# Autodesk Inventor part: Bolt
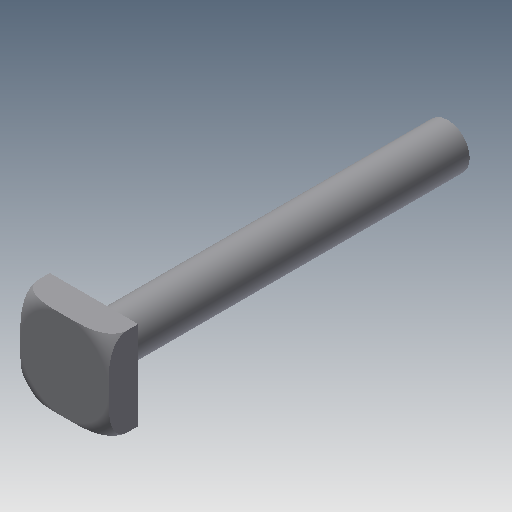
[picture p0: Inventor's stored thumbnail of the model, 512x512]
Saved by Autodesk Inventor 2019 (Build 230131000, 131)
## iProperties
Created: 2009-04
Part Number: Bolt
Document SubType Name: Modeling
Designer: Sham
Density: 1 g/cm^3
Material: Generic
Appearance: Default
Author: Sham
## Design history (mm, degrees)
sketch "Sketch1"
  geometry: L1 (-12, 12)-(12, 12); L2 (12, 12)-(12, -12); L3 (12, -12)-(-12, -12); L4 (-12, -12)-(-12, 12); 1 further point
  constraints: 8 end point, 2 parallel, 2 perpendicular, 1 horizontal, 1 other
  dimensions: "d0" = 24 distance of L1.start L1.end; "d1" = 12 distance from line of L2 point (0, 0); "d2" = 12 distance from line of L1 point (0, 0)
extrude "Extrusion1" new body sketch "Sketch1" distance "d3" = 8; taper "d4" = 0 deg
sketch "Sketch2"
  geometry: C1 r 6 at (0, 0)
  constraints: 1 centre point
  dimensions: "d5" = 12 diameter of C1
extrude "Extrusion2" join sketch "Sketch2" distance "d6" = 96; taper "d7" = 0 deg
workpoint "Work Point1"
workplane "Work Plane1"
sketch "Sketch3"
  geometry: L1 (33.941, 5)-(33.941, 6); L2 (28.941, 0)-(28.405, 0); L3 (16.971, 125.007)-(16.971, -22.043) reference; A1 r 5 centre (28.941, 5) between (28.941, 0) and (33.941, 5); 1 further point
  constraints: 4 end point, 2 point on circle, 2 point on line, 2 tangent, 1 centre point, 1 perpendicular
  dimensions: "d10" = 5 radius of A1
revolve "Revolution1" sketch "Sketch3" stored, may be unused: angle "d12" = 90 deg
body "Solid1"
other parameters: "d11" = 90 deg
